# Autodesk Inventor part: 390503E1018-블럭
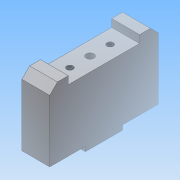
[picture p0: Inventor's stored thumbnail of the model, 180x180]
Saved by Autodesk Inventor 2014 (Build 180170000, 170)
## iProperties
Created: 2019-05
Part Number: 390503E1018-블럭
Material: 일반
Document SubType Name: Modeling
Designer: NET
Density: 1 g/cm^3
Appearance: 기본값
Mass: 52.6309 g
Surface Area: 109.486 cm^2
Volume: 52.6309 cm^3
Author: NET
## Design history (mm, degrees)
sketch "스케치1"
  geometry: L1 (0, 0)-(0, 45); L2 (0, 45)-(12, 45); L3 (12, 45)-(12, 40); L4 (12, 40)-(58, 40); L5 (58, 40)-(58, 45); L6 (58, 45)-(70, 45); L7 (70, 45)-(70, 0); L8 (70, 0)-(47, 0); L9 (47, 0)-(47, -3); L10 (47, -3)-(23, -3); L11 (23, -3)-(23, 0); L12 (23, 0)-(0, 0)
  constraints: 24 end point, 12 parallel, 2 perpendicular, 1 vertical
  dimensions: "d1" = 45 distance of L6.end L7.end; "d2" = 46 distance of L3.end L4.end; "d3" = 70 distance of L6.end L1.end; "d4" = 12 distance of L5.end L6.end; "d5" = 5 distance of L4.end L5.end; "d6" = 23 distance of L11.end L1.start; "d7" = 3 distance of L10.end L11.end
extrude "돌출1" new body sketch "스케치1" distance "d8" = 18; taper "d9" = 0 deg
chamfer "모따기1" distance "d10" = 5; stored, may be unused: second distance "d11" = 2, angle "d12" = 45 deg
sketch "스케치2"
  geometry: L1 (0, -7)-(0, 0) reference; L2 (0, -12)-(18, -12) reference; 2 further points
  constraints: 1 vertical alignment
  dimensions: "d13" = 9 distance from line of L1 point (9, 10); "d14" = 22 distance from line of point (9, 10) L2; "d15" = 26 distance of point (9, 36) point (9, 10)
hole "구멍1" sketch "스케치2" at (9, 10), (9, 36) diameter "d16" = 4.134; stored, may be unused: countersink angle "d20" = 90 deg, drill point angle "d22" = 118 deg; dims "d17" = 8, "d18" = 4, "d19" = 2, "d21" = 10
sketch "스케치3"
  geometry: L1 (-18, 0)-(-18, 23) reference; L2 (0, 0)-(-18, 0) reference; L3 (0, 47)-(0, 23) reference; L4 (0, 47)-(-18, 47) reference; L5 (-18, 23)-(-18, 47) reference; L6 (0, 23)-(-18, 23) reference; L7 (0, 70)-(0, 47) reference; L8 (0, 70)-(-18, 70) reference; L9 (-18, 47)-(-18, 70) reference; L10 (0, 47)-(-18, 47) reference; 2 further points
  dimensions: "d23" = 9 distance from line of point (-9, 9) L2; "d24" = 9 distance from line of point (-9, 9) L1; "d26" = 9 distance from line of L8 point (-9, 61); "d27" = 9 horizontal distance of L7.start point (-9, 61)
hole "구멍2" sketch "스케치3" at (-9, 9), (-9, 61) diameter "d28" = 4.134; stored, may be unused: countersink angle "d32" = 90 deg, drill point angle "d34" = 118 deg; dims "d29" = 8, "d30" = 4, "d31" = 2, "d33" = 10
sketch "스케치4"
  geometry: L1 (0, 0)-(0, 46) reference; L2 (0, -12)-(18, -12) reference; 1 further point
  dimensions: "d35" = 35 distance from line of point (9, 23) L2; "d36" = 9 distance from line of point (9, 23) L1
hole "구멍3" sketch "스케치4" at (9, 23) diameter "d37" = 5; stored, may be unused: countersink angle "d41" = 90 deg, drill point angle "d43" = 118 deg; dims "d38" = 8, "d39" = 4, "d40" = 2, "d42" = 5
sketch "스케치5"
  geometry: L1 (0, 24)-(0, 0) reference; L2 (0, 47)-(-18, 47) reference; 2 further points
  dimensions: "d44" = 35 distance from line of point (-9, 12) L2; "d45" = 9 distance from line of point (-9, 12) L1
hole "구멍4" sketch "스케치5" at (-9, 12) diameter "d46" = 5; stored, may be unused: countersink angle "d50" = 90 deg, drill point angle "d52" = 118 deg; dims "d47" = 8, "d48" = 4, "d49" = 2, "d51" = 5
node "솔리드1"
node "투영된 루프1"
node "투영된 루프2"
